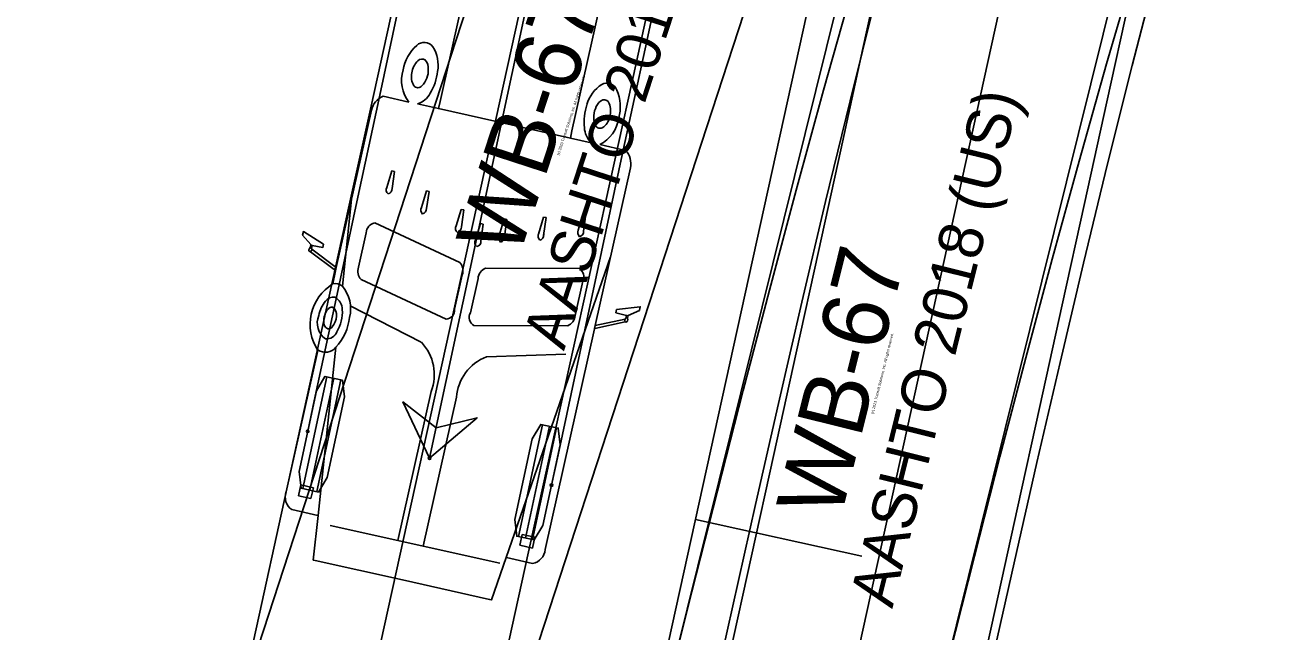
# Model space of a CAD drawing. Extents: x -69 to 14108008, y -6 to 8640172.
# Drawn here: x 14107700.55 to 14107740.71, y 8639756.9 to 8639776.36 of the extents above; entities that cross this region are included whole.
import ezdxf

# ---------------------------------------------------------------- set-up
doc = ezdxf.new("R2010")
doc.units = 0
for name, color, linetype in [('Alignment', 7, 'Continuous'), ('AutoTurn2', 7, 'Continuous'), ('AutoTurn3', 7, 'Continuous'), ('AutoTurn4', 7, 'Continuous'), ('AutoTurn5', 7, 'Continuous'), ('TextAlignmentSml', 7, 'Continuous')]:
    doc.layers.add(name, color=color, linetype=linetype)

msp = doc.modelspace()

# ---------------------------------------------------------------- linework, layer by layer
at = {"layer": 'Alignment'}
msp.add_line((14107732.613, 8639808.607), (14107547.946, 8638968.472), dxfattribs=at)
at = {"layer": 'AutoTurn2'}
for points in [[(14107721.115, 8639754.96), (14107721.925, 8639758.191), (14107722.741, 8639761.419), (14107723.567, 8639764.642), (14107724.407, 8639767.858), (14107725.264, 8639771.068), (14107726.14, 8639774.268), (14107727.041, 8639777.458), (14107727.968, 8639780.636), (14107728.926, 8639783.799), (14107729.917, 8639786.947), (14107730.945, 8639790.078), (14107732.012, 8639793.189), (14107733.121, 8639796.279), (14107734.274, 8639799.346), (14107735.474, 8639802.388), (14107736.723, 8639805.403)], [(14107730.168, 8639756.118), (14107730.979, 8639759.324), (14107731.797, 8639762.516), (14107732.627, 8639765.693), (14107733.47, 8639768.853), (14107734.331, 8639771.996), (14107735.212, 8639775.118), (14107736.117, 8639778.219), (14107737.049, 8639781.297), (14107738.011, 8639784.351), (14107739.005, 8639787.38), (14107740.035, 8639790.381), (14107741.102, 8639793.354), (14107742.209, 8639796.297), (14107743.358, 8639799.21), (14107744.551, 8639802.09), (14107745.789, 8639804.936)], [(14107725.866, 8639738.913), (14107725.887, 8639738.908), (14107725.904, 8639738.976), (14107727.269, 8639744.477), (14107738.627, 8639790.281), (14107734.502, 8639791.304), (14107730.377, 8639792.327), (14107719.019, 8639746.523), (14107717.655, 8639741.022), (14107717.638, 8639740.953), (14107717.659, 8639740.948)]]:
    msp.add_lwpolyline(points, dxfattribs=at)
at = {"layer": 'AutoTurn3'}
msp.add_line((14107725.593, 8639748.722), (14107738.539, 8639807.621), dxfattribs=at)
for points in [[(14107723.117, 8639756.089), (14107723.832, 8639759.343), (14107724.547, 8639762.597), (14107725.262, 8639765.851), (14107725.978, 8639769.105), (14107726.693, 8639772.359), (14107727.408, 8639775.613), (14107728.123, 8639778.868), (14107728.839, 8639782.122), (14107729.554, 8639785.376), (14107730.269, 8639788.63), (14107730.985, 8639791.884), (14107731.7, 8639795.138), (14107732.415, 8639798.392), (14107733.13, 8639801.646), (14107733.846, 8639804.9), (14107734.561, 8639808.154), (14107735.319, 8639811.429), (14107736.171, 8639814.696), (14107737.115, 8639817.948), (14107738.151, 8639821.182), (14107739.278, 8639824.393), (14107740.494, 8639827.578), (14107741.8, 8639830.733)], [(14107730.93, 8639754.372), (14107731.645, 8639757.626), (14107732.361, 8639760.88), (14107733.076, 8639764.134), (14107733.791, 8639767.388), (14107734.506, 8639770.642), (14107735.222, 8639773.896), (14107735.937, 8639777.15), (14107736.652, 8639780.404), (14107737.368, 8639783.658), (14107738.083, 8639786.912), (14107738.798, 8639790.166), (14107739.513, 8639793.42), (14107740.229, 8639796.675), (14107740.944, 8639799.929), (14107741.659, 8639803.183), (14107742.374, 8639806.437)], [(14107722.512, 8639754.486), (14107723.233, 8639757.738), (14107723.961, 8639760.986), (14107724.698, 8639764.231), (14107725.447, 8639767.472), (14107726.212, 8639770.707), (14107726.995, 8639773.935), (14107727.8, 8639777.154), (14107728.63, 8639780.364), (14107729.488, 8639783.563), (14107730.377, 8639786.749), (14107731.3, 8639789.922), (14107732.26, 8639793.078), (14107733.259, 8639796.217), (14107734.3, 8639799.338), (14107735.385, 8639802.438), (14107736.516, 8639805.517)], [(14107731.53, 8639755.89), (14107732.253, 8639759.118), (14107732.984, 8639762.336), (14107733.725, 8639765.541), (14107734.479, 8639768.731), (14107735.249, 8639771.906), (14107736.039, 8639775.064), (14107736.851, 8639778.204), (14107737.688, 8639781.325), (14107738.553, 8639784.425), (14107739.449, 8639787.503), (14107740.378, 8639790.559), (14107741.343, 8639793.59), (14107742.346, 8639796.596), (14107743.389, 8639799.576), (14107744.473, 8639802.529), (14107745.601, 8639805.453)]]:
    msp.add_lwpolyline(points, dxfattribs=at)
at = {"layer": 'AutoTurn4'}
for p, q in [((14107725.743, 8639819.502), (14107713.52, 8639762.474)), ((14107712.033, 8639774.076), (14107712.858, 8639773.892)), ((14107713.803, 8639773.681), (14107718.03, 8639772.737)), ((14107718.975, 8639772.526), (14107719.8, 8639772.342)), ((14107712.153, 8639771.157), (14107712.311, 8639771.685)), ((14107712.311, 8639771.685), (14107712.399, 8639771.665)), ((14107712.399, 8639771.665), (14107712.318, 8639771.12)), ((14107713.258, 8639770.515), (14107713.416, 8639771.043)), ((14107713.416, 8639771.043), (14107713.503, 8639771.024)), ((14107713.503, 8639771.024), (14107713.422, 8639770.479)), ((14107711.019, 8639770.779), (14107710.723, 8639767.988)), ((14107714.373, 8639769.924), (14107714.531, 8639770.452)), ((14107714.531, 8639770.452), (14107714.619, 8639770.432)), ((14107714.619, 8639770.432), (14107714.537, 8639769.887)), ((14107715.752, 8639769.616), (14107715.91, 8639770.144)), ((14107715.91, 8639770.144), (14107715.998, 8639770.124)), ((14107715.998, 8639770.124), (14107715.916, 8639769.579)), ((14107717.008, 8639769.652), (14107717.171, 8639770.205)), ((14107717.171, 8639770.205), (14107717.259, 8639770.185)), ((14107717.259, 8639770.185), (14107717.173, 8639769.616)), ((14107718.285, 8639769.788), (14107718.443, 8639770.316)), ((14107718.443, 8639770.316), (14107718.531, 8639770.296)), ((14107718.531, 8639770.296), (14107718.449, 8639769.751)), ((14107711.487, 8639769.7), (14107711.241, 8639768.596)), ((14107714.486, 8639768.749), (14107711.761, 8639770.018)), ((14107714.995, 8639769.469), (14107715.153, 8639769.997)), ((14107715.153, 8639769.997), (14107715.241, 8639769.977)), ((14107715.241, 8639769.977), (14107715.159, 8639769.432)), ((14107709.728, 8639769.298), (14107709.71, 8639769.319)), ((14107709.756, 8639769.293), (14107709.728, 8639769.298)), ((14107719.315, 8639768.927), (14107715.975, 8639759.289)), ((14107710.529, 8639768.583), (14107710.507, 8639768.485)), ((14107715.314, 8639768.564), (14107718.32, 8639768.554)), ((14107711.321, 8639768.199), (14107714.046, 8639766.93)), ((14107714.32, 8639767.248), (14107714.567, 8639768.352)), ((14107714.826, 8639767.135), (14107715.072, 8639768.239)), ((14107718.433, 8639768.149), (14107718.187, 8639767.046)), ((14107713.254, 8639766.193), (14107710.972, 8639767.354)), ((14107719.826, 8639767.045), (14107719.853, 8639767.037)), ((14107719.853, 8639767.037), (14107719.879, 8639767.049)), ((14107717.945, 8639766.72), (14107714.939, 8639766.731)), ((14107718.825, 8639766.731), (14107718.803, 8639766.633)), ((14107708.924, 8639761.396), (14107709.936, 8639765.929)), ((14107710.516, 8639766.032), (14107709.944, 8639760.635)), ((14107715.342, 8639765.727), (14107717.888, 8639765.807)), ((14107709.454, 8639761.497), (14107710.223, 8639765.082)), ((14107709.678, 8639761.449), (14107710.447, 8639765.034)), ((14107709.902, 8639761.401), (14107710.671, 8639764.986)), ((14107712.503, 8639759.833), (14107713.569, 8639764.607)), ((14107713.317, 8639759.651), (14107714.383, 8639764.425)), ((14107716.369, 8639759.961), (14107717.137, 8639763.546)), ((14107716.593, 8639759.913), (14107717.361, 8639763.498)), ((14107716.817, 8639759.865), (14107717.585, 8639763.45)), ((14107709.393, 8639761.614), (14107709.315, 8639761.267)), ((14107709.315, 8639761.267), (14107709.718, 8639761.177)), ((14107709.795, 8639761.524), (14107709.393, 8639761.614)), ((14107709.718, 8639761.177), (14107709.795, 8639761.524)), ((14107710.337, 8639760.317), (14107715.766, 8639759.104)), ((14107716.409, 8639759.683), (14107716.487, 8639760.03)), ((14107716.812, 8639759.593), (14107716.409, 8639759.683)), ((14107716.487, 8639760.03), (14107716.89, 8639759.941)), ((14107716.89, 8639759.941), (14107716.812, 8639759.593))]:
    msp.add_line(p, q, dxfattribs=at)
for points in [[(14107724.402, 8639830.154), (14107723.454, 8639826.846), (14107722.598, 8639823.512), (14107721.834, 8639820.161), (14107721.108, 8639816.83), (14107720.389, 8639813.51), (14107719.673, 8639810.199), (14107718.961, 8639806.896), (14107718.251, 8639803.599), (14107717.544, 8639800.309), (14107716.838, 8639797.023), (14107716.134, 8639793.742), (14107715.43, 8639790.464), (14107714.728, 8639787.189), (14107714.026, 8639783.916), (14107713.325, 8639780.646), (14107712.624, 8639777.378), (14107711.924, 8639774.111), (14107711.223, 8639770.845), (14107710.524, 8639767.58), (14107709.824, 8639764.316), (14107709.614, 8639763.337)], [(14107732.65, 8639830.011), (14107731.703, 8639826.931), (14107730.841, 8639823.826), (14107730.066, 8639820.699), (14107729.375, 8639817.546), (14107728.703, 8639814.357), (14107728.026, 8639811.159), (14107727.344, 8639807.951), (14107726.659, 8639804.736), (14107725.971, 8639801.514), (14107725.282, 8639798.287), (14107724.591, 8639795.055), (14107723.898, 8639791.819), (14107723.204, 8639788.579), (14107722.51, 8639785.336), (14107721.815, 8639782.091), (14107721.119, 8639778.844), (14107720.423, 8639775.595), (14107719.726, 8639772.344), (14107719.029, 8639769.093), (14107718.332, 8639765.84), (14107717.635, 8639762.586), (14107717.425, 8639761.61)], [(14107713.133, 8639773.831), (14107713.803, 8639773.681), (14107713.855, 8639773.913), (14107716.113, 8639784.026), (14107718.226, 8639783.555), (14107720.339, 8639783.083), (14107718.082, 8639772.97), (14107718.03, 8639772.737), (14107718.7, 8639772.588)], [(14107709.692, 8639769.233), (14107709.71, 8639769.318), (14107709.709, 8639769.32), (14107709.451, 8639769.622), (14107709.449, 8639769.624), (14107709.475, 8639769.74), (14107709.477, 8639769.74), (14107710.123, 8639769.333), (14107710.1, 8639769.232), (14107709.757, 8639769.293), (14107709.756, 8639769.292), (14107709.739, 8639769.214), (14107709.739, 8639769.213), (14107709.739, 8639769.212), (14107709.743, 8639769.174), (14107709.743, 8639769.174), (14107710.529, 8639768.583), (14107711.657, 8639773.635)], [(14107719.953, 8639771.783), (14107718.825, 8639766.731), (14107719.787, 8639766.931), (14107719.788, 8639766.932), (14107719.807, 8639766.964), (14107719.808, 8639766.965), (14107719.808, 8639766.966), (14107719.826, 8639767.044), (14107719.825, 8639767.045), (14107719.489, 8639767.136), (14107719.511, 8639767.237), (14107720.27, 8639767.331), (14107720.271, 8639767.33), (14107720.245, 8639767.214), (14107720.243, 8639767.213), (14107719.881, 8639767.05), (14107719.879, 8639767.048), (14107719.859, 8639766.963)], [(14107710.413, 8639768.062), (14107710.506, 8639768.478), (14107710.499, 8639768.492), (14107709.706, 8639769.093)], [(14107719.787, 8639766.843), (14107718.813, 8639766.636), (14107718.801, 8639766.626), (14107717.221, 8639759.543)], [(14107713.52, 8639762.474), (14107715.043, 8639763.77), (14107713.729, 8639763.451), (14107712.662, 8639764.28), (14107713.52, 8639762.474)], [(14107716.819, 8639759.1), (14107715.983, 8639759.287), (14107715.974, 8639759.287), (14107715.504, 8639757.932), (14107715.443, 8639757.946), (14107712.648, 8639758.57), (14107709.854, 8639759.193), (14107709.792, 8639759.208), (14107709.943, 8639760.633), (14107709.935, 8639760.637), (14107709.099, 8639760.824)]]:
    msp.add_lwpolyline(points, dxfattribs=at)
for points in [[(14107709.958, 8639761.389), (14107709.398, 8639761.509), (14107709.338, 8639762.047), (14107709.891, 8639764.628), (14107710.167, 8639765.094), (14107710.726, 8639764.974), (14107710.787, 8639764.436), (14107710.234, 8639761.855)], [(14107713.52, 8639762.474), (14107715.043, 8639763.77), (14107713.729, 8639763.451), (14107712.662, 8639764.28)], [(14107716.873, 8639759.853), (14107716.313, 8639759.973), (14107716.252, 8639760.511), (14107716.806, 8639763.092), (14107717.082, 8639763.558), (14107717.641, 8639763.438), (14107717.702, 8639762.9), (14107717.149, 8639760.319)]]:
    msp.add_lwpolyline(points, close=True, dxfattribs=at)
for centre in [(14107709.614, 8639763.337), (14107713.52, 8639762.474), (14107717.425, 8639761.61)]:
    msp.add_circle(centre, 0.0417, dxfattribs=at)
for centre, radius, start, end in [((14107713.347, 8639775.459), 0.346, 37.0095, 134.0225), ((14107714.062, 8639774.662), 1.416, 132.4192, 169.4871), ((14107712.657, 8639775.071), 1.136, 350.1305, 31.6513), ((14107713.756, 8639774.588), 1.136, 162.994, 217.7853), ((14107713.609, 8639774.741), 0.664, 134.2897, 172.5114), ((14107713.272, 8639775.1), 0.172, 49.963, 137.1136), ((14107712.747, 8639774.918), 0.732, 316.007, 2.2414), ((14107713.118, 8639774.984), 0.362, 354.0777, 43.1187), ((14107713.456, 8639774.695), 0.522, 165.2457, 212.4099), ((14107712.056, 8639775.069), 1.73, 328.7901, 353.5886), ((14107713.146, 8639774.521), 0.169, 218.8622, 318.9809), ((14107712.895, 8639774.519), 0.729, 289.0927, 331.6067), ((14107719.659, 8639773.508), 1.136, 123.1792, 164.6999), ((14107719.198, 8639774.152), 0.346, 20.8079, 117.821), ((14107718.213, 8639773.735), 1.416, 345.3434, 22.4112), ((14107712.261, 8639773.5), 0.619, 111.5755, 167.4172), ((14107720.201, 8639773.251), 1.73, 161.2419, 186.0404), ((14107719.512, 8639773.408), 0.732, 152.589, 198.8235), ((14107719.204, 8639773.625), 0.362, 111.7118, 160.7528), ((14107719.114, 8639773.795), 0.172, 17.7168, 104.8674), ((14107718.656, 8639773.615), 0.664, 342.319, 20.5408), ((14107718.458, 8639773.538), 1.136, 297.0452, 351.8364), ((14107718.775, 8639773.507), 0.522, 302.4206, 349.5847), ((14107719.208, 8639773.11), 0.729, 183.2237, 225.7377), ((14107718.981, 8639773.218), 0.169, 195.8495, 295.9683), ((14107719.349, 8639771.918), 0.619, 347.4132, 43.2549), ((14107712.285, 8639771.071), 0.157, 146.7596, 233.8692), ((14107712.134, 8639771.119), 0.184, 288.57, 0.462), ((14107713.389, 8639770.429), 0.157, 146.7596, 233.8692), ((14107713.238, 8639770.477), 0.184, 288.57, 0.462), ((14107711.819, 8639769.691), 0.332, 100.0718, 178.4938), ((14107714.504, 8639769.838), 0.157, 146.7596, 233.8692), ((14107714.353, 8639769.886), 0.184, 288.57, 0.462), ((14107718.451, 8639769.708), 0.184, 154.3684, 226.2604), ((14107718.294, 8639769.729), 0.157, 280.9612, 8.0709), ((14107715.126, 8639769.383), 0.157, 146.7596, 233.8692), ((14107715.004, 8639769.41), 0.157, 280.9612, 8.0709), ((14107715.918, 8639769.536), 0.184, 154.3684, 226.2604), ((14107715.761, 8639769.557), 0.157, 280.9612, 8.0709), ((14107717.179, 8639769.597), 0.184, 154.3684, 226.2604), ((14107717.022, 8639769.618), 0.157, 280.9612, 8.0709), ((14107709.705, 8639769.145), 0.0522, 166.2978, 271.1524), ((14107709.762, 8639769.151), 0.108, 130.3916, 176.574), ((14107711.604, 8639768.463), 0.387, 159.8504, 223.0824), ((14107714.203, 8639768.485), 0.387, 339.8529, 43.0799), ((14107715.458, 8639768.205), 0.387, 111.7505, 174.9776), ((14107718.129, 8639768.283), 0.332, 336.3366, 54.7586), ((14107711.221, 8639766.76), 1.53, 121.908, 212.917), ((14107710.499, 8639767.723), 0.347, 49.7424, 104.553), ((14107709.852, 8639767.259), 1.136, 346.1198, 39.9223), ((14107710.975, 8639766.845), 1.03, 140.2389, 168.6254), ((14107710.442, 8639767.321), 0.317, 83.2654, 144.8578), ((14107710.393, 8639767.142), 0.17, 85.0843, 139.1486), ((14107710.277, 8639767.084), 0.263, 346.3501, 60.2521), ((14107710.28, 8639767.243), 0.44, 359.2095, 63.0223), ((14107710.554, 8639766.81), 0.634, 157.9991, 234.0008), ((14107710.717, 8639766.876), 0.589, 140.1707, 183.1535), ((14107709.958, 8639767.051), 0.575, 320.4903, 357.0607), ((14107709.263, 8639767.187), 1.704, 317.3359, 353.244), ((14107709.534, 8639767.145), 1.189, 328.5464, 4.4357), ((14107714.025, 8639767.225), 0.296, 274.134, 4.4317), ((14107715.083, 8639766.989), 0.296, 150.3988, 240.6965), ((14107717.801, 8639767.08), 0.387, 291.7481, 354.98), ((14107719.761, 8639766.919), 0.108, 338.2564, 24.4389), ((14107710.35, 8639766.823), 0.223, 174.6501, 244.2526), ((14107710.21, 8639766.662), 0.366, 265.4676, 337.9485), ((14107710.274, 8639766.778), 0.158, 262.3864, 323.8992), ((14107719.81, 8639766.889), 0.0522, 243.678, 348.5326), ((14107712.153, 8639765.151), 1.517, 338.9953, 43.4227), ((14107710.181, 8639766.294), 0.425, 235.4782, 322.0145), ((14107715.895, 8639764.315), 1.517, 111.4078, 175.8352), ((14107709.378, 8639761.221), 0.486, 159.0011, 234.9523), ((14107716.736, 8639759.579), 0.486, 279.8782, 355.8293)]:
    msp.add_arc(centre, radius, start, end, dxfattribs=at)
for centre, major_axis, start_param, end_param in [((14107709.698, 8639769.163), (-0.017, -0.0763), 2.398717, 3.668019), ((14107709.698, 8639769.163), (-0.017, -0.0763), 0.569648, 1.840391), ((14107719.823, 8639766.902), (0.017, 0.0763), 1.301202, 2.571945), ((14107719.823, 8639766.902), (-0.017, -0.0763), 2.615166, 3.884468)]:
    msp.add_ellipse(centre, major_axis=major_axis, ratio=0.544872, start_param=start_param, end_param=end_param, dxfattribs=at)
at = {"layer": 'AutoTurn5'}
msp.add_line((14107724.986, 8639815.832), (14107706.661, 8639732.465), dxfattribs=at)
for points in [[(14107718.866, 8639806.556), (14107718.136, 8639803.255), (14107717.409, 8639799.961), (14107716.684, 8639796.673), (14107715.961, 8639793.39), (14107715.239, 8639790.111), (14107714.519, 8639786.835), (14107713.799, 8639783.562), (14107713.079, 8639780.292), (14107712.361, 8639777.024), (14107711.643, 8639773.758), (14107710.925, 8639770.493), (14107710.208, 8639767.229), (14107709.49, 8639763.967), (14107708.773, 8639760.706), (14107708.057, 8639757.445), (14107707.34, 8639754.185)], [(14107726.525, 8639804.27), (14107725.823, 8639801.056), (14107725.119, 8639797.837), (14107724.412, 8639794.612), (14107723.703, 8639791.382), (14107722.994, 8639788.147), (14107722.283, 8639784.91), (14107721.571, 8639781.669), (14107720.858, 8639778.427), (14107720.145, 8639775.181), (14107719.432, 8639771.935), (14107718.718, 8639768.686), (14107718.004, 8639765.437), (14107717.29, 8639762.186), (14107716.575, 8639758.934), (14107715.86, 8639755.682)], [(14107722.349, 8639800.281), (14107722.329, 8639800.288), (14107722.307, 8639800.221), (14107720.549, 8639794.833), (14107705.918, 8639749.967), (14107709.958, 8639748.649), (14107713.999, 8639747.332), (14107728.63, 8639792.198), (14107730.387, 8639797.586), (14107730.409, 8639797.653), (14107730.388, 8639797.66)]]:
    msp.add_lwpolyline(points, dxfattribs=at)
at = {"layer": 'TextAlignmentSml'}
msp.add_line((14107722.04, 8639760.507), (14107727.373, 8639759.335), dxfattribs=at)

# ---------------------------------------------------------------- texts
at = {"layer": 'AutoTurn2'}
for s, height, p in [('AASHTO 2018 (US)', 1.41667, (14107728.348, 8639757.63)), ('WB-67', 2.125, (14107726.68, 8639760.468)), ('(c) 2023 Transoft Solutions, Inc. All rights reserved.', 0.085, (14107727.746, 8639763.884))]:
    msp.add_text(s, height=height, rotation=76.0735, dxfattribs=at).set_placement(p)
at = {"layer": 'AutoTurn5'}
for s, height, p in [('AASHTO 2018 (US)', 1.41667, (14107717.825, 8639765.895)), ('WB-67', 2.125, (14107716.366, 8639768.845)), ('(c) 2023 Transoft Solutions, Inc. All rights reserved.', 0.085, (14107717.675, 8639772.176))]:
    msp.add_text(s, height=height, rotation=71.9382, dxfattribs=at).set_placement(p)

doc.saveas('drawing.dxf')
